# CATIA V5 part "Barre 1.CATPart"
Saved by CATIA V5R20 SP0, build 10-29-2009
Part number: Barre 1
Bounding box of the stored display mesh (mm): x -2.5 to 2.5, y -2.5 to 42.5, z 5 to 7.5
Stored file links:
  C:\Users\Admin\Desktop\IAO\Barre 1.CATPart
  C:\Users\Admin\Desktop\IAO\Ass_4barres.CATProduct
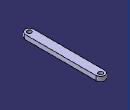
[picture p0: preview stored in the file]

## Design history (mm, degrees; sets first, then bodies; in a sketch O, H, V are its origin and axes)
Set1
  Sketch1 on Plane1, origin (0, 0, 0), H (1, 0, 0), V (0, 1, 0)
    construction line L1 (0, 40) -> (0, 0)
    point P1 (0, 40)
    point P2 (0, 0)
    line L2 (2.5, 40) -> (2.5, 0)
    line L3 (-2.5, 0) -> (-2.5, 40)
    arc A1 centre (0, 0) radius 2.5 from (2.5, 0) to (-2.5, 0) cw
    arc A2 centre (0, 40) radius 2.5 from (-2.5, 40) to (2.5, 40) cw
    reference projected point E1 (0, 40) from Point1
    reference projected point E2 (0, 0) from Point2
    distance L1 L2 = 2.5
    vertical: L1 V
    tangency: A1 L2, A2 L2, A1 L3, A2 L3
    coincidence: P1 E1, P2 E2
Set2
  Plane1 "Plan ref": linked copy from another document
  Point1 "Point B": linked copy from another document
  Point2 "Point A": linked copy from another document
Body1 (main body)
  Pad1: profile Sketch1, direction (0, 0, 1), length 7.5, opposite side length -5
  Sketch2 on end face of Pad1, origin (-0.9605, 41.2339, 7.5), H (1, 0, 0), V (0, 1, 0)
    point P1 (0.9605, -1.2339)
    reference projected arc E1 centre (0.9605, -1.2339) radius 2.5 from (3.4605, -1.2339) to (-1.5395, -1.2339) ccw from edge [face of Pad1 from Sketch1.A2 | end face of Pad1]
    concentricity: P1 E1
  Hole1: placed by Sketch2, at (0, 40, 7.5) direction (0, 0, -1), diameter 2.5, through (limit type 6)
  Sketch3 on end face of Pad1, origin (1.2271, 3.3889, 7.5), H (1, 0, 0), V (0, 1, 0)
    point P1 (-1.2271, -3.3889)
    reference projected arc E1 centre (-1.2271, -3.3889) radius 2.5 from (-3.7271, -3.3889) to (1.2729, -3.3889) ccw from edge [face of Pad1 from Sketch1.A1 | end face of Pad1]
    concentricity: P1 E1
  Hole2: placed by Sketch3, at (0, 0, 7.5) direction (0, 0, -1), diameter 2.5, through (limit type 6)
